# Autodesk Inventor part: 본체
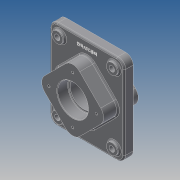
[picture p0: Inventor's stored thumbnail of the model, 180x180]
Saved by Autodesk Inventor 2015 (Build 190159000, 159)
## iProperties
Created: 2026-07
Part Number: 본체
Material: 일반
Document SubType Name: Modeling
Designer: user
Density: 1 g/cm^3
Appearance: 기본값
Author: user
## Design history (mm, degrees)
sketch "스케치1"
  geometry: L1 (75, 90)-(-75, 90); L2 (-75, 90)-(-75, -90); L3 (-75, -90)-(75, -90); L4 (75, -90)-(75, 90); L5 (75, 90)-(-75, -90); L6 (-75, 90)-(75, -90); 1 further point
  constraints: 12 end point, 2 midpoint, 2 parallel, 1 horizontal, 1 perpendicular
  dimensions: "d0" = 150 distance of L1.start L1.end; "d1" = 180 distance of L1.end L2.end
extrude "돌출1" new body sketch "스케치1" distance "d2" = 18; taper "d3" = 0 deg
sketch "스케치2"
  geometry: L1 (0, 70.711)-(-70.711, 0); L2 (-70.711, 0)-(0, -70.711); L3 (0, -70.711)-(70.711, 0); L4 (0, 70.711)-(70.711, 0); 1 further point
  constraints: 8 end point, 2 horizontal alignment, 2 vertical alignment, 1 perpendicular
  dimensions: "d4" = 100 distance of L2.end L3.end; "d5" = 100 distance of L1.start L3.end; "d6" = 100 distance of L1.start L1.end
extrude "돌출2" join sketch "스케치2" distance "d7" = 29; taper "d9" = 0 deg; dims "d8" = 41, "d10" = 0
sketch "스케치3"
  geometry: C1 r 11 at (-55, 70); 2 further points
  constraints: 1 centre point, 1 coincident
  dimensions: "d11" = 55 horizontal distance of point (-55, 70) point (0, 0); "d12" = 70 vertical distance of point (0, 0) point (-55, 70); "d13" = 22 diameter of C1
extrude "돌출3" join sketch "스케치3" distance "d14" = 5; taper "d15" = 0 deg
hole "구멍1" diameter "d18" = 11; stored, may be unused: countersink angle "d22" = 82 deg, drill point angle "d24" = 0 deg; dims "d16" = 10, "d17" = 10, "d19" = 6, "d20" = 3.023, "d21" = 2, "d23" = 8
sketch "스케치4"
  geometry: 2 further points
  constraints: 1 coincident
hole "구멍2" sketch "스케치4" at (0, 0) diameter "d31" = 54; stored, may be unused: countersink angle "d35" = 82 deg, drill point angle "d37" = 0 deg; dims "d32" = 6, "d33" = 62, "d34" = 22, "d36" = 8
hole "구멍3" diameter "d40" = 62; stored, may be unused: countersink angle "d44" = 82 deg, drill point angle "d46" = 0 deg; dims "d38" = 10, "d39" = 10, "d41" = 6, "d42" = 62, "d43" = 22, "d45" = 22
sketch "스케치5"
  geometry: 2 further points
  constraints: 1 vertical alignment
  dimensions: "d47" = 48 distance of point (0, 0) point (0, 48)
hole "구멍4" sketch "스케치5" at (0, 48) diameter "d48" = 4.917; stored, may be unused: countersink angle "d52" = 82 deg, drill point angle "d54" = 118 deg; dims "d49" = 10, "d50" = 62, "d51" = 22, "d53" = 13
sketch "스케치6"
  geometry: 2 further points
  constraints: 1 vertical alignment
  dimensions: "d58" = 48 distance of point (0, 0) point (0, -48)
hole "구멍5" sketch "스케치6" at (0, -48) diameter "d59" = 4.917; stored, may be unused: countersink angle "d63" = 82 deg, drill point angle "d65" = 118 deg; dims "d60" = 10, "d61" = 62, "d62" = 22, "d64" = 13
sketch "스케치7"
  geometry: L1 (75, 90)-(-75, 90) reference; 2 further points
  constraints: 1 vertical alignment, 1 other
  dimensions: "d69" = 15 distance from line of point (0, 75) L1
feature "엠보싱1" sketch "스케치7" dims "d0" = 150, "d1" = 180, "d70" = 0.5, "d71" = 0
fillet "모깎기1" dims "d72" = 15
fillet "모깎기2" dims "d73" = 20
fillet "모깎기3" dims "d74" = 20
fillet "모깎기4" dims "d75" = 3
fillet "모깎기5" dims "d76" = 3
fillet "모깎기7" dims "d78" = 3
fillet "모깎기8" dims "d79" = 3
chamfer "모따기1" distance "d80" = 1; stored, may be unused: second distance "d81" = 2, angle "d82" = 45 deg
fillet "모깎기9" dims "d83" = 1
node "솔리드1"
pattern_linear "직사각형 패턴1"
pattern_circular "원형 패턴1" dims angle "d56" = 360 deg
pattern_circular "원형 패턴2" dims angle "d67" = 360 deg
